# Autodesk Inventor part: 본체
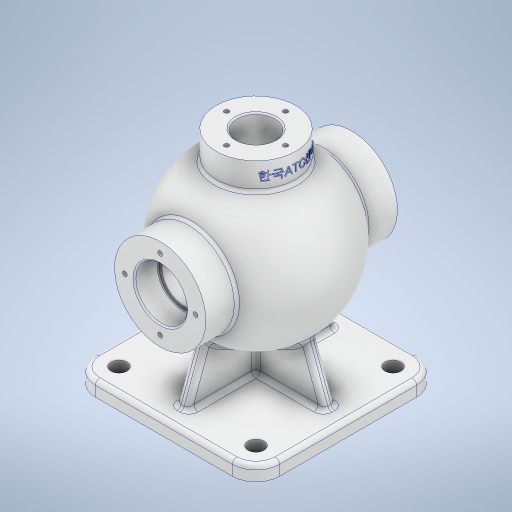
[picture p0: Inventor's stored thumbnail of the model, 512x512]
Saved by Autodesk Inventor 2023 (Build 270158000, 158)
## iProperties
Created: 2023-07
Part Number: 본체
Material: 알루미늄 6061
Document SubType Name: Modeling
Designer: Owner
Density: 2.7 g/cm^3
Appearance: 알루미늄 - 평지
Mass: 1526.72 g
Surface Area: 1173.82 cm^2
Volume: 565.453 cm^3
Author: Owner
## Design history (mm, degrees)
sketch "스케치1"
  geometry: L1 (-62.5, 62.5)-(-62.5, -62.5); L2 (-62.5, -62.5)-(62.5, -62.5); L3 (62.5, -62.5)-(62.5, 62.5); L4 (62.5, 62.5)-(-62.5, 62.5); L5 (-62.5, 62.5)-(62.5, -62.5); L6 (-62.5, -62.5)-(62.5, 62.5); 1 further point
  constraints: 12 end point, 2 midpoint, 2 parallel, 1 perpendicular, 1 vertical
  dimensions: "d0" = 125 distance of L1.end L2.end; "d1" = 125 distance of L2.end L3.end
extrude "돌출1" new body sketch "스케치1" distance "d2" = 10; taper "d3" = 0 deg
sketch "스케치3"
  geometry: L1 (85, 65)-(54, 65); L2 (54, -65)-(85, -65); L3 (85, -65)-(85, 65); L4 (54, 65)-(54, 44.215); L5 (54, -44.215)-(54, -65); A1 r 54 centre (85, 0) between (54, 44.215) and (54, -44.215); 2 further points
  constraints: 10 end point, 3 parallel, 2 midpoint, 2 perpendicular, 2 point on circle, 1 centre point, 1 collinear, 1 horizontal, 1 horizontal alignment
  dimensions: "d10" = 54 radius of A1; "d11" = 130 distance between parallel lines of L1 L2; "d12" = 62 diameter of L4 L3; "d13" = 62 diameter of L5 L3; "d14" = 85 distance of point (0, 0) A1.centre
revolve "회전1" sketch "스케치3" stored, may be unused: angle "d15" = 90 deg
sketch "스케치17"
  geometry: L1 (10, -62.5)-(10, 62.5) reference; L2 (10, 50.5)-(95, 19.563); L3 (95, 19.563)-(95, -19.563); L4 (95, -19.563)-(10, -50.5); L5 (0, -62.5)-(10, -62.5) reference; L6 (0, 62.5)-(10, 62.5) reference; 1 further point
  constraints: 6 end point, 2 point on line, 1 parallel
  dimensions: "d99" = 12 distance of L1.start L4.end; "d100" = 20 deg angle of L4 L5; "d101" = 12 distance of L1.end L2.start; "d102" = 20 deg angle of L2 L6; "d103" = 85 distance between parallel lines of L1 L3
extrude "돌출9" join sketch "스케치17" stored distance "d104" = 8; taper "d105" = 0 deg
sketch "스케치18"
  geometry: L1 (62.5, 10)-(-62.5, 10) reference; L2 (50.5, 10)-(43.107, 30.313); L3 (62.5, 0)-(62.5, 10) reference; 1 further point
  constraints: 2 end point, 1 point on line
  dimensions: "d106" = 12 distance of L1.start L2.start; "d107" = 20 deg angle of L3 L2
feature "리브2" sketch "스케치18" dims "d108" = 1, "d109" = 8, "d110" = 0, "d111" = 0, "d112" = 1, "d113" = 1
sketch "스케치19"
  geometry: L1 (116, -65)-(54, -65) reference; L2 (54, -65)-(54, -44.215) reference; L3 (46.034, -37.385)-(10, -50.5) reference; L4 (10, -50.5)-(10, -62.5) reference; L5 (10, -62.5)-(0, -62.5) reference; L6 (0, -62.5)-(0, 62.5) reference; L7 (0, 62.5)-(10, 62.5) reference; L8 (10, 62.5)-(10, 50.5) reference; L9 (10, 50.5)-(46.034, 37.385) reference; L10 (54, 44.215)-(54, 65) reference; L11 (54, 65)-(116, 65) reference; L12 (116, 65)-(116, 44.215) reference; L13 (116, -44.215)-(116, -65) reference; L14 (116, 44.215)-(54, 44.215) reference; L15 (85, 44.215)-(85, -44.215); L16 (116, -44.215)-(54, -44.215) reference; A1 r 44 centre (85, 0) between (85, -44) and (85, 44); A2 r 54 centre (85, 0) between (46.034, -37.385) and (54, -44.215) reference; A3 r 54 centre (85, 0) between (54, 44.215) and (46.034, 37.385) reference; A4 r 54 centre (85, 0) between (116, -44.215) and (116, 44.215) reference; 1 further point
  constraints: 2 end point, 2 midpoint, 2 point on circle, 2 point on line, 1 centre point, 1 coincident
  dimensions: "d114" = 88 diameter of A1
revolve "회전3" sketch "스케치19" stored, may be unused: angle "d115" = 90 deg
sketch "스케치20"
  geometry: C1 r 31 at (0, 0) reference; C2 r 17.5 at (0, 0); 1 further point
  constraints: 1 centre point, 1 coincident
  dimensions: "d116" = 35 diameter of C2
extrude "돌출10" cut sketch "스케치20" stored distance "d117" = 32; taper "d118" = 0 deg
sketch "스케치21"
  geometry: C1 r 17.5 at (0, 0) reference; C2 r 15 at (0, 0); 1 further point
  constraints: 1 centre point, 1 coincident
  dimensions: "d119" = 30 diameter of C2
extrude "돌출11" cut sketch "스케치21" stored distance "d120" = 16; taper "d121" = 0 deg
node "작업 평면2"
sketch "스케치22"
  geometry: C1 r 27 at (0, 0); 1 further point
  constraints: 1 centre point, 1 coincident
  dimensions: "d123" = 54 diameter of C1
extrude "돌출12" join sketch "스케치22" stored distance "d124" = 10; taper "d125" = 0 deg
sketch "스케치23"
  geometry: C1 r 27 at (0, 0) reference; C2 r 13 at (0, 0)
  constraints: 1 centre point, 1 coincident
  dimensions: "d126" = 26 diameter of C2
extrude "돌출13" cut sketch "스케치23" stored distance "d127" = 10; taper "d128" = 0 deg
sketch "스케치24" dims "d129" = 48
  geometry: C1 r 31 at (0, 0) reference; 3 further points
  constraints: 1 coincident, 1 vertical alignment, 2 other
hole "구멍3" sketch "스케치24" at (0, 24) diameter "d130" = 3.242; stored, may be unused: countersink angle "d134" = 90 deg, drill point angle "d136" = 118 deg; dims "d131" = 12, "d132" = 4, "d133" = 2, "d135" = 15
sketch "스케치25" dims "d140" = 40
  geometry: C1 r 27 at (0, 0) reference; 2 further points
  constraints: 1 coincident, 1 horizontal alignment, 2 other
hole "구멍4" sketch "스케치25" at (20, 0) diameter "d141" = 3.242; stored, may be unused: countersink angle "d145" = 90 deg, drill point angle "d147" = 118 deg; dims "d142" = 9, "d143" = 4, "d144" = 2, "d146" = 11
fillet "모깎기8" dims "d151" = 16
fillet "모깎기9" dims "d152" = 3
sketch "스케치26"
  geometry: C1 r 5.5 at (46.5, 46.5); C2 r 5.5 at (46.5, -46.5); C3 r 5.5 at (-46.5, -46.5); C4 r 5.5 at (-46.5, 46.5); A1 r 13 centre (46.5, 46.5) between (59.5, 46.5) and (46.5, 59.5) reference; A2 r 13 centre (-46.5, 46.5) between (-46.5, 59.5) and (-59.5, 46.5) reference; A3 r 13 centre (-46.5, -46.5) between (-59.5, -46.5) and (-46.5, -59.5) reference; A4 r 13 centre (46.5, -46.5) between (46.5, -59.5) and (59.5, -46.5) reference; 1 further point
  constraints: 4 centre point, 4 coincident
  dimensions: "d153" = 11 diameter of C1; "d154" = 11 diameter of C2; "d155" = 11 diameter of C3; "d156" = 11 diameter of C4
extrude "돌출14" cut sketch "스케치26" extent not by distance; stored distance "d157" = 0; taper "d158" = 0 deg
fillet "모깎기10" dims "d159" = 3
fillet "모깎기11" dims "d160" = 3
fillet "모깎기12" dims "d161" = 3
fillet "모깎기13" dims "d162" = 3
fillet "모깎기14" dims "d163" = 3
chamfer "모따기4" distance "d164" = 1; stored, may be unused: second distance "d165" = 2, angle "d166" = 45 deg
chamfer "모따기5" distance "d167" = 1; stored, may be unused: second distance "d168" = 2, angle "d169" = 45 deg
chamfer "모따기6" distance "d170" = 1; stored, may be unused: second distance "d171" = 2, angle "d172" = 45 deg
node "작업 평면3"
sketch "스케치27"
  geometry: L1 (0, 46.5)-(0, -46.5) reference; L2 (150, -27)-(150, 27) reference; 3 further points
  constraints: 1 horizontal alignment, 1 midpoint, 1 other
  dimensions: "d175" = 9 distance from line of point (141, 0) L2
feature "엠보싱1" sketch "스케치27" dims "d176" = 0.5, "d177" = 0
fillet "모깎기16" dims "d178" = 0.6
feature "β耀δ耀ζ耀θ耀κ耀μ耀ξ耀π耀" dims "d0" = 125, "d1" = 125, "d2" = 10, "d3" = 0, "d10" = 54, "d11" = 130, "d12" = 62, "d13" = 62, "d14" = 85, "d15" = 90 deg, "d99" = 12, "d100" = 20 deg, "d101" = 12, "d102" = 20 deg, "d103" = 85, "d104" = 8, "d105" = 0, "d106" = 12, "d107" = 20 deg, "d108" = 1, "d109" = 8, "d110" = 0, "d111" = 0, "d112" = 1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
node "솔리드1"
mirror "미러4"
mirror "미러5"
pattern_circular "원형 패턴3" dims angle "d138" = 360 deg
mirror "미러6"
pattern_circular "원형 패턴4" dims angle "d149" = 360 deg
node "절단 모서리 투영3"
feature "A9D066F2-1C7D-4E18-AEED-F7BC21143FA4" dims "d130" = 3.242, "d131" = 12, "d132" = 4, "d133" = 2, "d134" = 90 deg, "d135" = 15, "d136" = 118 deg
